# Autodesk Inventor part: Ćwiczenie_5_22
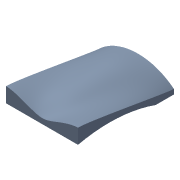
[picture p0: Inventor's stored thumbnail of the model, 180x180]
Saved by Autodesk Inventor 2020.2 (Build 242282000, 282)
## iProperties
Created: 2005-03
Part Number: Ćwiczenie_5_22
Document SubType Name: Modeling
Designer: F.Stasiak
Manufacturer: Standard
Standards Organization: Custom
Density: 1 g/cm^3
Material: Ogólny
Appearance: Stalowoniebieska - jasna
Manager: www.cadconsulting.pl
Company: Fabian Stasiak CAD Consulting
Author: F.Stasiak
Subject: Zbiór ćwiczeń. Autodesk Inventor 2020. Kurs podstawowy
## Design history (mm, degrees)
sketch "Szkic1"
  geometry: L1 (-75, 200)-(75, 200); L2 (75, 200)-(75, 0); L3 (75, 0)-(-75, 0); L4 (-75, 0)-(-75, 200); 2 further points
  constraints: 8 end point, 2 parallel, 1 coincident, 1 horizontal, 1 midpoint, 1 perpendicular
  dimensions: "d0" = 150 distance of L2.end L3.end; "d1" = 200 distance of L3.end L1.start
extrude "Wyciągnięcie proste1" new body sketch "Szkic1" distance "d2" = 40; taper "d3" = 0 deg
sketch "Szkic2"
  geometry: L1 (150, 40)-(0, 40) reference; L2 (150, 0)-(150, 40) reference; L3 (0, 0)-(0, 40) reference; L4 (150, 0)-(0, 0) reference; L5 (75, 40)-(75, 0); A1 r 120 centre (75, -83.675) between (150, 10) and (0, 10)
  constraints: 2 end point, 2 midpoint, 2 point on circle, 2 point on line, 1 centre point
  dimensions: "d4" = 120 radius of A1; "d15" = 10 distance of A1.end L3.start; "d16" = 10 distance of L2.start A1.start (= d15)
sketch "Szkic3"
  geometry: L1 (0, 40)-(-150, 40) reference; L2 (0, 0)-(-150, 0) reference; L3 (-75, 40)-(-75, 0); L4 (-164.747, 40)-(-135.253, 40); L5 (-14.747, 40)-(14.747, 40); A1 r 36.108 centre (-150, 3.892) between (-136.348, 37.32) and (-163.652, 37.32); A2 r 36.462 centre (0, 3.538) between (13.671, 37.34) and (-13.671, 37.34); 5 further points
  constraints: 7 midpoint, 6 end point, 2 centre point, 2 collinear, 2 horizontal, 2 point on circle, 10 other
  dimensions: "d5" = 25 horizontal distance of point (-75, 20) point (-100, 26); "d6" = 25 horizontal distance of point (-50, 26) point (-75, 20) (= d5); "d7" = 6 vertical distance of point (-75, 20) point (-50, 26); "d8" = 6 vertical distance of point (-75, 20) point (-100, 26) (= d7); "d19" = 10 dimension on L4.start L4.end; "d20" = 10 dimension on L5.start L5.end
node "Punkt konstrukcyjny1"
node "Punkt konstrukcyjny2"
sketch "Szkic4"
  geometry: 6 further points
  constraints: 4 other
feature "PowWyciągnięciaZłożonego1" sketch "Szkic4" dims "d24" = 20, "d25" = 90 deg, "d26" = 20, "d27" = 90 deg, "d28" = 0, "d29" = 90 deg
feature "Zastąp powierzchnię1"
sketch "Szkic5"
  geometry: L1 (0, 0)-(200, 0) reference; L2 (38.042, 0)-(200, 0); L3 (200, 0)-(200, 9.058); A1 r 289.672 centre (134.548, -273.123) between (200, 9.058) and (38.042, 0)
  constraints: 4 end point, 2 point on circle, 1 centre point, 1 collinear, 1 perpendicular, 1 point on line
extrude "Wyciągnięcie proste2" cut sketch "Szkic5" extent not by distance; stored distance "d22" = 10; taper "d23" = 0 deg
node "Bryła1"
node "Korpusy bryłowe"
node "Korpusy powierzchniowe"
body "Srf1"
